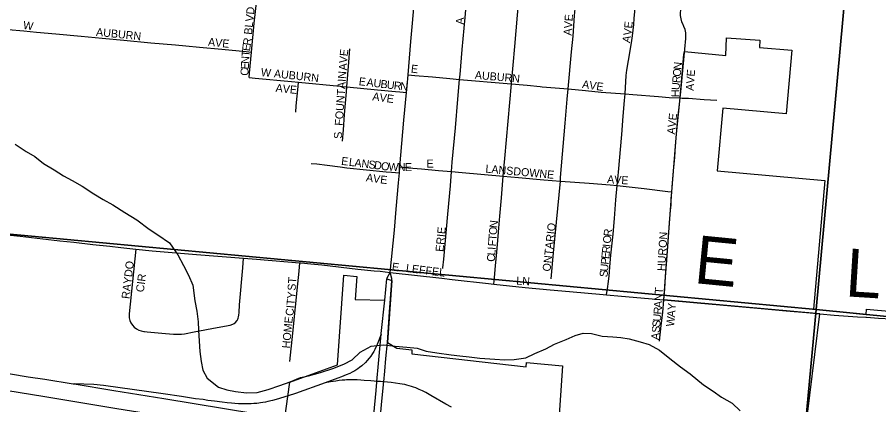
# Model space of a CAD drawing. Extents: x -209 to 4852, y 0 to 905.
# Drawn here: x 106.4 to 126.79, y 230.91 to 240.07 of the extents above; entities that cross this region are included whole.
import ezdxf

# ---------------------------------------------------------------- set-up
doc = ezdxf.new("R2010")
doc.units = 0
for name, color, linetype in [('GM_X_Airport_Location_Class_2', 7, 'Continuous'), ('GM_X_Airport_Location_Class_3', 7, 'Continuous'), ('GM_X_County_Road', 7, 'Continuous'), ('GM_X_County_ROW', 7, 'Continuous'), ('GM_X_County_Subdivision_Text', 7, 'Continuous'), ('GM_X_Interstate_Location', 7, 'Continuous'), ('GM_X_Minor_River', 7, 'Continuous'), ('GM_X_Rail_Line', 7, 'Continuous'), ('GM_X_Rail_Line_Text', 7, 'Continuous'), ('GM_X_Township_Road', 7, 'Continuous'), ('GM_X_Township_Text', 7, 'Continuous'), ('GM_X_US_Location', 7, 'Continuous')]:
    doc.layers.add(name, color=color, linetype=linetype)

msp = doc.modelspace()

# ---------------------------------------------------------------- linework, layer by layer
at = {"layer": 'GM_X_Airport_Location_Class_2'}
for points in [[(116.868, 238.6), (116.877, 238.715), (116.929, 239.305), (116.995, 240.065), (117.036, 240.54), (117.056, 240.755)], [(111.943, 239.248), (112.006, 239.926), (112.066, 240.492)], [(118.095, 238.496), (118.172, 239.382), (118.241, 240.123), (118.277, 240.556), (118.285, 240.643)], [(119.439, 238.377), (119.519, 239.249), (119.553, 239.62), (119.59, 240.115), (119.618, 240.426), (119.627, 240.52)], [(120.785, 238.256), (120.791, 238.41), (120.8, 238.544), (120.81, 238.692), (120.827, 238.82), (120.903, 239.273), (120.945, 239.522), (120.962, 239.631), (120.977, 239.761), (120.989, 239.895), (121.003, 240.037), (121.015, 240.204), (121.029, 240.406)], [(122.092, 238.161), (122.105, 238.309), (122.222, 239.566), (122.224, 239.622), (122.219, 239.701), (122.204, 239.778), (122.179, 239.852), (122.167, 239.878), (122.16, 239.892), (122.13, 239.962), (122.11, 240.035), (122.1, 240.109), (122.099, 240.173), (122.109, 240.298)], [(106.101, 239.791), (106.184, 239.783), (106.548, 239.749), (106.85, 239.721), (107.311, 239.677), (107.91, 239.621), (108.405, 239.575), (108.915, 239.527), (109.557, 239.468), (110.142, 239.414), (110.388, 239.391), (110.71, 239.361), (111.241, 239.312), (111.817, 239.26), (111.943, 239.248)], [(111.888, 238.644), (111.897, 238.748), (111.943, 239.248)], [(114.198, 238.425), (114.242, 239.01), (114.265, 239.322)], [(111.888, 238.644), (112.027, 238.63), (112.887, 238.549), (113.053, 238.533)], [(115.646, 238.707), (115.804, 238.694), (116.229, 238.657), (116.639, 238.618), (116.868, 238.6)], [(112.987, 237.824), (113.001, 237.975), (113.044, 238.436), (113.053, 238.533)], [(113.053, 238.533), (114.04, 238.44), (114.103, 238.434), (114.198, 238.425)], [(114.097, 237.138), (114.118, 237.405), (114.146, 237.769), (114.188, 238.304), (114.198, 238.425)], [(114.198, 238.425), (114.923, 238.356), (115.35, 238.315), (115.451, 238.306), (115.61, 238.291)], [(116.675, 236.419), (116.695, 236.646), (116.768, 237.455), (116.827, 238.131), (116.868, 238.6)], [(116.868, 238.6), (117.997, 238.504), (118.095, 238.496)], [(117.901, 236.312), (117.941, 236.726), (118.095, 238.496)], [(118.095, 238.496), (118.37, 238.471), (118.469, 238.461), (118.774, 238.433), (118.825, 238.428), (119.439, 238.377)], [(119.252, 236.192), (119.259, 236.279), (119.368, 237.569), (119.416, 238.135), (119.439, 238.377)], [(119.439, 238.377), (119.851, 238.338), (120.222, 238.299), (120.785, 238.256)], [(120.597, 236.088), (120.611, 236.243), (120.634, 236.49), (120.65, 236.674), (120.705, 237.294), (120.742, 237.728), (120.773, 238.1), (120.785, 238.256)], [(120.785, 238.256), (120.966, 238.243), (121.578, 238.196), (121.828, 238.172), (122.092, 238.161)], [(113.351, 236.615), (113.491, 236.601), (113.736, 236.572), (114.043, 236.532)], [(114.043, 236.532), (114.197, 236.51), (115.132, 236.411), (115.257, 236.403), (115.441, 236.39)], [(115.453, 236.53), (115.659, 236.511), (115.969, 236.484), (116.366, 236.447), (116.675, 236.419)], [(116.469, 234.126), (116.47, 234.141), (116.49, 234.348), (116.524, 234.707), (116.59, 235.416), (116.648, 236.087), (116.675, 236.419)], [(116.675, 236.419), (116.925, 236.399), (117.901, 236.312)], [(117.678, 233.759), (117.692, 233.917), (117.717, 234.191), (117.746, 234.513), (117.762, 234.694), (117.789, 234.987), (117.819, 235.367), (117.858, 235.799), (117.901, 236.312)], [(117.901, 236.312), (118.259, 236.279), (118.861, 236.228), (119.252, 236.192)], [(119.035, 233.883), (119.093, 234.501), (119.161, 235.228), (119.252, 236.192)], [(119.252, 236.192), (119.938, 236.147), (120.434, 236.104), (120.597, 236.088)], [(120.348, 233.506), (120.374, 233.704), (120.382, 233.765), (120.404, 233.951), (120.433, 234.261), (120.451, 234.447), (120.501, 234.942), (120.534, 235.314), (120.566, 235.749), (120.597, 236.088)], [(120.597, 236.088), (121.239, 236.024), (121.794, 235.951), (121.888, 235.938)], [(97.241, 235.873), (97.891, 235.793), (98.261, 235.752), (98.939, 235.676), (99.802, 235.584), (100.48, 235.511), (101.651, 235.382), (102.761, 235.262), (104.303, 235.099), (104.674, 235.067), (105.538, 234.984), (106.464, 234.895), (107.407, 234.786), (107.734, 234.749), (108.188, 234.698)], [(108.188, 234.698), (108.585, 234.653)], [(108.585, 234.653), (108.844, 234.623), (109.203, 234.587)], [(109.203, 234.587), (109.043, 233.054), (109.042, 233.021), (109.047, 232.959), (109.063, 232.898), (109.088, 232.84), (109.122, 232.787), (109.165, 232.741), (109.215, 232.702), (109.27, 232.673), (109.329, 232.652), (109.392, 232.642), (109.41, 232.641), (109.474, 232.634), (109.909, 232.593), (110.095, 232.578), (110.211, 232.573), (110.281, 232.575), (110.356, 232.587), (110.587, 232.63), (111.132, 232.731), (111.435, 232.789), (111.498, 232.809), (111.529, 232.828), (111.554, 232.847), (111.598, 232.9), (111.619, 232.929), (111.628, 232.954), (111.637, 232.983), (111.644, 233.026), (111.648, 233.087), (111.66, 233.27), (111.732, 234.145), (111.75, 234.371)], [(109.203, 234.587), (109.586, 234.549), (110.637, 234.458), (111.75, 234.371)], [(111.75, 234.371), (112.061, 234.347), (113.078, 234.265)], [(113.078, 234.265), (113.058, 234.069), (113.027, 233.764), (112.914, 232.602), (112.841, 231.931)], [(113.078, 234.265), (113.116, 234.262), (113.343, 234.242), (113.603, 234.214), (114.457, 234.115), (114.841, 234.076), (114.984, 234.062), (115.221, 234.037)], [(115.221, 234.037), (116.448, 233.898), (116.691, 233.871), (117.553, 233.772), (117.678, 233.759)], [(117.678, 233.759), (118.416, 233.679), (119.011, 233.626), (119.466, 233.585), (120.268, 233.514), (120.348, 233.506)], [(120.348, 233.506), (120.7, 233.474), (121.705, 233.387)], [(121.598, 232.409), (121.64, 232.779), (121.677, 233.086), (121.705, 233.387)]]:
    msp.add_lwpolyline(points, dxfattribs=at)
at = {"layer": 'GM_X_County_Road'}
for points in [[(106.347, 237.065), (106.603, 236.897), (106.814, 236.774), (107.017, 236.613), (107.273, 236.459), (107.492, 236.321), (107.695, 236.206), (107.936, 236.075), (108.207, 235.898), (108.433, 235.76), (108.659, 235.637), (108.945, 235.453), (109.224, 235.276), (109.518, 235.062), (109.721, 234.923), (109.999, 234.739), (110.201, 234.45), (110.328, 234.198), (110.447, 233.97), (110.552, 233.734), (110.602, 233.362), (110.645, 233.119), (110.681, 232.869), (110.687, 232.671), (110.701, 232.413), (110.721, 232.163), (110.75, 231.928), (110.786, 231.723), (110.891, 231.532), (111.161, 231.325), (111.358, 231.263), (111.562, 231.224), (111.826, 231.191)], [(111.826, 231.191), (112.076, 231.197), (112.334, 231.271), (112.614, 231.36), (112.857, 231.449), (113.1, 231.553), (113.289, 231.589), (113.577, 231.67), (113.866, 231.767), (114.124, 231.863), (114.321, 231.968), (114.512, 232.148), (114.77, 232.29), (115.065, 232.326), (115.345, 232.293), (115.617, 232.269), (115.866, 232.244), (116.078, 232.174), (116.327, 232.134), (116.667, 232.086), (116.871, 232.062), (117.091, 232.037), (117.348, 232.012), (117.703, 231.987), (117.93, 231.97), (118.157, 231.976), (118.437, 232.019), (118.65, 232.116), (118.908, 232.228), (119.113, 232.34), (119.386, 232.451), (119.606, 232.548), (119.796, 232.6), (119.992, 232.591), (120.241, 232.528), (120.491, 232.511), (120.687, 232.494), (120.884, 232.462), (121.141, 232.392), (121.352, 232.33), (121.601, 232.199), (121.841, 232), (122.097, 231.801), (122.323, 231.64), (122.639, 231.379), (122.872, 231.226), (123.068, 231.088), (123.316, 230.942), (123.512, 230.766)]]:
    msp.add_lwpolyline(points, dxfattribs=at)
at = {"layer": 'GM_X_County_ROW'}
for points in [[(121.705, 233.387), (122.489, 233.317), (123.296, 233.242), (123.917, 233.187), (124.6, 233.129), (125.079, 233.086), (125.245, 233.071), (125.398, 233.057), (125.734, 233.028), (126.29, 232.988), (126.487, 232.976)], [(126.487, 232.976), (126.499, 232.975), (126.783, 232.957), (127.705, 232.905)]]:
    msp.add_lwpolyline(points, dxfattribs=at)
at = {"layer": 'GM_X_County_Subdivision_Text'}
for points in [[(115.221, 234.037), (115.326, 235.036), (115.367, 235.531), (115.42, 236.151), (115.441, 236.39), (115.453, 236.53), (115.549, 237.638), (115.61, 238.291), (115.624, 238.443), (115.646, 238.707), (115.713, 239.496), (115.807, 240.549), (115.834, 240.862), (115.976, 242.531), (116.061, 243.523), (116.135, 244.391), (116.149, 244.542), (116.196, 245.082)], [(114.801, 230.255), (114.893, 231.247), (114.909, 231.439), (114.911, 231.46), (114.946, 231.879), (115.011, 232.574), (115.012, 232.59), (115.096, 233.38), (115.147, 233.883), (115.149, 233.895), (115.153, 233.905), (115.221, 234.037)], [(115.255, 233.723), (115.264, 233.843), (115.266, 233.869), (115.266, 233.881), (115.264, 233.893), (115.221, 234.037)], [(114.888, 229.537), (114.908, 229.75), (114.914, 229.809), (114.926, 229.94), (114.95, 230.206), (114.952, 230.23), (114.994, 230.651), (115.034, 231.067), (115.063, 231.377), (115.068, 231.425), (115.071, 231.447), (115.096, 231.699), (115.124, 232.002), (115.159, 232.376), (115.208, 233.103), (115.255, 233.723)]]:
    msp.add_lwpolyline(points, dxfattribs=at)
at = {"layer": 'GM_X_Minor_River'}
for points in [[(106.979, 255.688), (127.195, 253.652), (125.307, 233.161), (105.036, 235.054)], [(147.511, 251.706), (145.448, 231.165), (125.307, 233.161), (127.195, 253.652)], [(105.036, 235.054), (125.307, 233.161), (123.431, 212.988), (103.184, 214.918)], [(125.307, 233.161), (145.448, 231.165), (143.519, 211.007), (123.431, 212.988)]]:
    msp.add_lwpolyline(points, close=True, dxfattribs=at)
at = {"layer": 'GM_X_Rail_Line'}
for points in [[(115.011, 232.574), (114.944, 232.408), (114.94, 232.397), (114.915, 232.334), (114.892, 232.281), (114.862, 232.215), (114.838, 232.169), (114.806, 232.115), (114.767, 232.058), (114.729, 232.006), (114.68, 231.95), (114.636, 231.902), (114.552, 231.824), (114.501, 231.785), (114.457, 231.754), (114.39, 231.712), (114.322, 231.678), (114.265, 231.649), (114.184, 231.614), (114.069, 231.566), (113.983, 231.533), (113.687, 231.427), (112.98, 231.171), (112.81, 231.117), (112.523, 231.028), (112.436, 231.005), (112.33, 230.981), (112.273, 230.971), (112.209, 230.959), (112.155, 230.951), (112.111, 230.945), (112.065, 230.94), (111.997, 230.935), (111.937, 230.93), (111.853, 230.927), (111.75, 230.927), (111.63, 230.932), (111.545, 230.937), (111.466, 230.944), (111.361, 230.954), (111.244, 230.968), (111.062, 230.991), (110.908, 231.011), (110.795, 231.027), (110.616, 231.05), (110.28, 231.101), (109.851, 231.166), (108.435, 231.361), (108.205, 231.385), (107.972, 231.395), (107.744, 231.398)], [(115.071, 231.447), (114.992, 231.453), (114.911, 231.46), (114.847, 231.465), (114.767, 231.473), (114.611, 231.484), (114.531, 231.49), (114.444, 231.495), (114.351, 231.498), (114.297, 231.499), (114.239, 231.499), (114.193, 231.496), (114.147, 231.492), (114.084, 231.485), (114.017, 231.477), (113.934, 231.464), (113.811, 231.445), (113.687, 231.427)], [(116.672, 230.847), (116.541, 230.921), (116.188, 231.129), (116.069, 231.193), (115.992, 231.232), (115.912, 231.27), (115.832, 231.304), (115.779, 231.324), (115.725, 231.342), (115.675, 231.358), (115.619, 231.373), (115.571, 231.384), (115.508, 231.395), (115.449, 231.405), (115.353, 231.42), (115.248, 231.435), (115.246, 231.435), (115.157, 231.441), (115.071, 231.447)]]:
    msp.add_lwpolyline(points, dxfattribs=at)
at = {"layer": 'GM_X_Rail_Line_Text'}
for points in [[(95.901, 232.909), (99.91, 232.247), (102.8, 231.787), (107, 231.106), (108.753, 230.822), (109.994, 230.618), (112.682, 230.182)], [(105.765, 231.715), (106.657, 231.57), (107.052, 231.51), (107.721, 231.402), (107.744, 231.398), (108.681, 231.246), (109.869, 231.051), (112.738, 230.585)]]:
    msp.add_lwpolyline(points, dxfattribs=at)
at = {"layer": 'GM_X_Township_Text'}
for points in [[(121.888, 235.938), (121.905, 236.157), (121.931, 236.438), (121.96, 236.761), (121.979, 237.026), (122, 237.316), (122.024, 237.587), (122.05, 237.819), (122.065, 237.942), (122.092, 238.161)], [(122.092, 238.161), (122.136, 238.159), (122.212, 238.158), (122.287, 238.156), (122.653, 238.126), (122.96, 238.106)], [(121.705, 233.387), (121.723, 233.645), (121.734, 233.795), (121.745, 233.945), (121.765, 234.225), (121.78, 234.435), (121.796, 234.652), (121.827, 235.096), (121.847, 235.313), (121.863, 235.497), (121.873, 235.623), (121.876, 235.775), (121.888, 235.938)]]:
    msp.add_lwpolyline(points, dxfattribs=at)
at = {"layer": 'GM_X_US_Location'}
for points in [[(125.042, 230.172), (125.398, 233.057), (121.705, 233.387), (121.888, 235.938), (122, 237.316), (122.092, 238.161), (122.178, 239.19), (122.188, 239.259), (123.169, 239.169), (123.189, 239.583), (123.973, 239.531), (123.965, 239.358), (124.734, 239.289), (124.598, 237.783), (123.096, 237.918), (122.962, 236.437), (125.514, 236.207), (125.242, 233.164), (126.492, 233.042), (126.501, 233.167), (127.729, 233.056)], [(112.595, 229.626), (112.848, 231.437), (113.976, 231.849), (114.123, 233.973), (114.437, 233.941), (114.393, 233.396), (115.096, 233.38), (115.147, 233.883), (115.264, 233.843), (115.159, 232.376), (115.383, 232.245), (115.735, 232.202), (115.735, 232.11), (118.444, 231.801), (118.451, 231.906), (119.306, 231.827), (119.183, 230.085)]]:
    msp.add_lwpolyline(points, dxfattribs=at)

# ---------------------------------------------------------------- texts
at = {"layer": 'GM_X_Airport_Location_Class_3'}
for s, height, rotation, p in [('BLVD', 0.1894, 83.9943, (111.95, 239.65)), ('A', 0.189, 89.0382, (116.966, 239.895)), ('AVE', 0.1894, 86.0569, (119.516, 239.632)), ('W', 0.189, 351.2507, (106.524, 239.798)), ('E', 0.189, 84.5486, (120.949, 239.798)), ('AUBURN', 0.1894, 354.2073, (108.255, 239.632)), ('V', 0.189, 83.5709, (120.93, 239.629)), ('AVE', 0.1894, 354.0932, (110.905, 239.398)), ('E', 0.189, 82.3277, (111.903, 239.26)), ('R', 0.189, 81.4938, (111.921, 239.392)), ('A', 0.189, 80.3598, (120.9, 239.453)), ('T', 0.189, 85.4054, (111.893, 239.13)), ('E', 0.189, 83.4019, (114.214, 239.14)), ('N', 0.189, 86.5982, (111.883, 238.964)), ('V', 0.189, 85.3398, (114.201, 238.976)), ('C', 0.189, 86.5979, (111.866, 238.682)), ('E', 0.189, 86.583, (111.875, 238.831)), ('W AUBURN', 0.1894, 353.9105, (112.156, 238.682)), ('A', 0.189, 89.4099, (114.199, 238.812)), ('E', 0.189, 352.8783, (115.706, 238.765)), ('O', 0.189, 84.4177, (122.099, 238.657)), ('N', 0.189, 84.4177, (122.116, 238.823)), ('AVE', 0.1894, 86.0571, (122.408, 238.326)), ('FOUNTAIN', 0.1894, 86.0804, (114.1, 237.499)), ('E', 0.189, 353.2511, (114.473, 238.465)), ('A', 0.189, 353.241, (114.655, 238.444)), ('AUBURN', 0.1894, 355.0275, (117.222, 238.615)), ('R', 0.189, 84.4296, (122.085, 238.507)), ('AVE', 0.1894, 354.094, (112.505, 238.308)), ('U', 0.189, 353.2427, (114.82, 238.424)), ('B', 0.189, 353.2485, (114.986, 238.404)), ('U', 0.189, 353.2601, (115.135, 238.387)), ('R', 0.189, 353.5188, (115.301, 238.367)), ('N', 0.189, 354.8851, (115.455, 238.35)), ('AVE', 0.1894, 351.8726, (119.759, 238.398)), ('U', 0.189, 85.0984, (122.071, 238.342)), ('AVE', 0.1894, 352.1471, (114.795, 238.109)), ('H', 0.189, 88.3606, (122.066, 238.178)), ('S', 0.189, 90, (114.083, 237.196)), ('E', 0.189, 352.9055, (114.056, 236.582)), ('L', 0.189, 352.9055, (114.238, 236.559)), ('A', 0.189, 352.8994, (114.37, 236.543)), ('N', 0.189, 352.9095, (114.536, 236.522)), ('S', 0.189, 352.9055, (114.701, 236.501)), ('D', 0.189, 352.8994, (114.834, 236.485)), ('O', 0.189, 352.9095, (114.999, 236.464)), ('W', 0.189, 357.2962, (115.18, 236.442)), ('N', 0.189, 0.0096, (115.406, 236.432)), ('E', 0.189, 0, (115.573, 236.432)), ('E', 0.189, 0, (116.085, 236.515)), ('LANSDOWNE', 0.1894, 354.7535, (117.473, 236.398)), ('A', 0.189, 351.5762, (114.643, 236.193)), ('V', 0.189, 351.8005, (114.808, 236.168)), ('E', 0.189, 353.3385, (114.979, 236.144)), ('AVE', 0.1894, 356.3077, (120.354, 236.148)), ('N', 0.189, 83.7141, (117.76, 235.078)), ('ONTARIO', 0.1894, 83.5584, (119.016, 234.05)), ('ERIE', 0.1894, 84.4755, (116.483, 234.516)), ('O', 0.189, 84.6156, (117.745, 234.913)), ('R', 0.189, 83.3058, (120.46, 234.878)), ('F', 0.189, 85.9047, (117.726, 234.648)), ('T', 0.189, 85.8978, (117.735, 234.781)), ('O', 0.189, 84.4177, (120.444, 234.713)), ('L', 0.189, 85.9118, (117.71, 234.432)), ('I', 0.189, 85.8879, (117.72, 234.565)), ('R', 0.189, 84.4054, (120.421, 234.48)), ('I', 0.189, 84.4482, (120.436, 234.63)), ('C', 0.189, 85.8919, (117.7, 234.282)), ('P', 0.189, 84.4456, (120.395, 234.215)), ('E', 0.189, 84.4172, (120.408, 234.348)), ('RAYDO', 0.1894, 83.0227, (109.05, 233.401)), ('E', 0.189, 352.8783, (115.256, 234.081)), ('LEFFEL', 0.1894, 353.0183, (115.589, 234.048)), ('U', 0.189, 84.4177, (120.379, 234.049)), ('CIR', 0.1894, 82.5728, (109.39, 233.559)), ('ST', 0.1894, 86.4258, (112.983, 233.598)), ('LN', 0.1894, 356.989, (118.204, 233.748)), ('S', 0.189, 84.4172, (120.366, 233.916)), ('CITY', 0.1894, 84.6403, (112.933, 233)), ('N', 0.189, 86.8123, (121.665, 233.356)), ('T', 0.189, 86.8287, (121.674, 233.522)), ('A', 0.189, 86.784, (121.655, 233.189)), ('Y', 0.189, 85.9448, (121.979, 233.137)), ('R', 0.189, 85.8551, (121.644, 233.036)), ('A', 0.189, 84.823, (121.964, 232.967)), ('HOME', 0.1894, 84.5582, (112.85, 232.233)), ('U', 0.189, 84.2538, (121.627, 232.865)), ('W', 0.189, 83.852, (121.94, 232.748)), ('S', 0.189, 84.173, (121.6, 232.599)), ('S', 0.189, 84.1711, (121.613, 232.732)), ('A', 0.189, 84.1546, (121.583, 232.433))]:
    msp.add_text(s, height=height, rotation=rotation, dxfattribs=at).set_placement(p)
at = {"layer": 'GM_X_Interstate_Location'}
for s, height, rotation, p in [('V', 0.189, 83.912, (121.981, 237.457)), ('E', 0.189, 83.8952, (121.999, 237.623)), ('A', 0.189, 84.6374, (121.966, 237.292)), ('HURON', 0.1894, 86.4958, (121.733, 234.064))]:
    msp.add_text(s, height=height, rotation=rotation, dxfattribs=at).set_placement(p)
at = {"layer": 'GM_X_Township_Road'}
for s, rotation, p in [('E', 354.4019, (122.395, 233.787)), ('L', 356.4234, (125.979, 233.472))]:
    msp.add_text(s, height=1.136, rotation=rotation, dxfattribs=at).set_placement(p)

doc.saveas('drawing.dxf')
